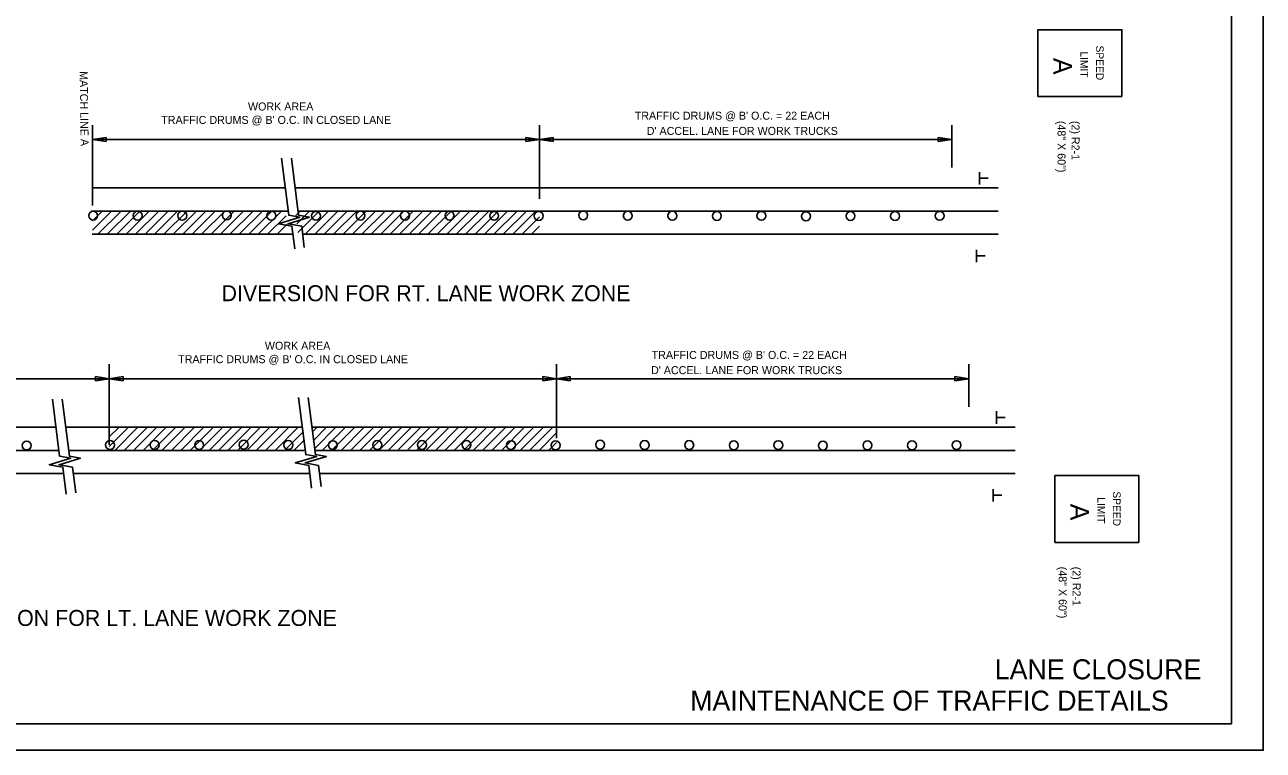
# Model space of a CAD drawing. Extents: x 1374897 to 1375063, y 381144 to 381251.
# Drawn here: x 1374970.4 to 1375063.2, y 381144.3 to 381198.7 of the extents above; entities that cross this region are included whole.
import ezdxf

# ---------------------------------------------------------------- set-up
doc = ezdxf.new("R2010")
doc.units = 0
for name, color, linetype in [('Default', 7, 'Continuous'), ('R_Border', 7, 'Continuous'), ('R_No Plot', 7, 'Continuous')]:
    doc.layers.add(name, color=color, linetype=linetype)

msp = doc.modelspace()

# ---------------------------------------------------------------- linework, layer by layer
at = {"layer": 'Default'}
for p, q in [((1374975.438, 381191.172), (1374975.438, 381185.137)), ((1375008.973, 381191.172), (1375008.973, 381185.637)), ((1375039.883, 381191.172), (1375039.883, 381187.98)), ((1374975.438, 381190.093), (1374976.468, 381190.248)), ((1374975.438, 381190.24), (1374975.438, 381185.137)), ((1374975.438, 381190.24), (1374975.438, 381185.137)), ((1374975.438, 381190.24), (1374975.438, 381185.137)), ((1374976.468, 381190.248), (1374976.468, 381189.938)), ((1375007.943, 381189.938), (1375007.943, 381190.247)), ((1375007.943, 381190.247), (1375008.973, 381190.093)), ((1375008.973, 381190.093), (1375010.003, 381190.248)), ((1375010.003, 381190.248), (1375010.003, 381189.938)), ((1375038.853, 381189.938), (1375038.853, 381190.248)), ((1375038.853, 381190.248), (1375039.883, 381190.093)), ((1375008.973, 381190.093), (1374975.438, 381190.093)), ((1374976.468, 381189.938), (1374975.438, 381190.093)), ((1375008.973, 381190.093), (1375007.943, 381189.938)), ((1375039.883, 381190.093), (1375008.973, 381190.093)), ((1375010.003, 381189.938), (1375008.973, 381190.093)), ((1375039.883, 381190.093), (1375038.853, 381189.938)), ((1375041.97, 381186.716), (1375041.97, 381187.643)), ((1375041.984, 381187.178), (1375042.617, 381187.178)), ((1374975.438, 381186.456), (1374989.916, 381186.456)), ((1374990.634, 381186.456), (1375008.973, 381186.456)), ((1375008.973, 381186.456), (1375043.362, 381186.456)), ((1374975.368, 381184.717), (1374990.061, 381184.717)), ((1374975.439, 381183.278), (1374976.878, 381184.717)), ((1374975.439, 381183.985), (1374976.171, 381184.717)), ((1374975.847, 381182.979), (1374977.585, 381184.717)), ((1374976.554, 381182.979), (1374978.347, 381184.773)), ((1374977.261, 381182.979), (1374978.999, 381184.717)), ((1374977.968, 381182.979), (1374979.706, 381184.717)), ((1374978.675, 381182.979), (1374980.413, 381184.717)), ((1374979.382, 381182.979), (1374981.12, 381184.717)), ((1374980.089, 381182.979), (1374981.827, 381184.717)), ((1374980.796, 381182.979), (1374982.535, 381184.717)), ((1374981.503, 381182.979), (1374983.242, 381184.717)), ((1374982.211, 381182.979), (1374983.949, 381184.717)), ((1374982.918, 381182.979), (1374984.656, 381184.717)), ((1374983.625, 381182.979), (1374985.363, 381184.717)), ((1374984.332, 381182.979), (1374986.07, 381184.717)), ((1374985.039, 381182.979), (1374986.777, 381184.717)), ((1374985.746, 381182.979), (1374987.484, 381184.717)), ((1374986.453, 381182.979), (1374988.191, 381184.717)), ((1374987.16, 381182.979), (1374988.899, 381184.717)), ((1374987.867, 381182.979), (1374989.606, 381184.717)), ((1374990.689, 381184.387), (1374991.02, 381184.717)), ((1374990.765, 381183.755), (1374991.727, 381184.717)), ((1374990.841, 381183.124), (1374992.434, 381184.717)), ((1374990.851, 381184.717), (1375008.973, 381184.717)), ((1374991.403, 381182.979), (1374993.141, 381184.717)), ((1374992.11, 381182.979), (1374993.848, 381184.717)), ((1374992.817, 381182.979), (1374994.555, 381184.717)), ((1374993.524, 381182.979), (1374995.263, 381184.717)), ((1374994.231, 381182.979), (1374995.97, 381184.717)), ((1374994.938, 381182.979), (1374996.677, 381184.717)), ((1374995.646, 381182.979), (1374997.384, 381184.717)), ((1374996.353, 381182.979), (1374998.091, 381184.717)), ((1374997.06, 381182.979), (1374998.798, 381184.717)), ((1374997.767, 381182.979), (1374999.505, 381184.717)), ((1374998.474, 381182.979), (1375000.212, 381184.717)), ((1374999.181, 381182.979), (1375000.919, 381184.717)), ((1374999.888, 381182.979), (1375001.626, 381184.717)), ((1375000.595, 381182.979), (1375002.334, 381184.717)), ((1375001.302, 381182.979), (1375003.041, 381184.717)), ((1375002.01, 381182.979), (1375003.748, 381184.717)), ((1375002.717, 381182.979), (1375004.455, 381184.717)), ((1375003.424, 381182.979), (1375005.162, 381184.717)), ((1375004.131, 381182.979), (1375005.869, 381184.717)), ((1375004.838, 381182.979), (1375006.576, 381184.717)), ((1375005.545, 381182.979), (1375007.283, 381184.717)), ((1375006.252, 381182.979), (1375007.99, 381184.717)), ((1375006.959, 381182.979), (1375008.698, 381184.717)), ((1375008.973, 381184.717), (1375043.362, 381184.717)), ((1374988.574, 381182.979), (1374989.963, 381184.367)), ((1374989.282, 381182.979), (1374990.039, 381183.736)), ((1375007.666, 381182.979), (1375008.973, 381184.286)), ((1374975.416, 381182.979), (1374990.477, 381182.979)), ((1374991.242, 381182.979), (1375008.973, 381182.979)), ((1375008.373, 381182.979), (1375008.973, 381183.579)), ((1375008.973, 381182.979), (1375043.362, 381182.979)), ((1375041.73, 381180.889), (1375041.73, 381181.817)), ((1375041.744, 381181.351), (1375042.377, 381181.351)), ((1374976.707, 381173.23), (1374976.707, 381167.195)), ((1375010.242, 381173.23), (1375010.242, 381167.695)), ((1375041.153, 381173.23), (1375041.153, 381170.038)), ((1374976.707, 381172.151), (1374945.797, 381172.151)), ((1374975.677, 381171.997), (1374975.677, 381172.306)), ((1374975.677, 381172.306), (1374976.707, 381172.151)), ((1374976.707, 381172.151), (1374975.677, 381171.997)), ((1374976.707, 381172.151), (1374977.737, 381172.306)), ((1374976.707, 381172.299), (1374976.707, 381167.195)), ((1374976.707, 381172.298), (1374976.707, 381167.195)), ((1374976.707, 381172.298), (1374976.707, 381167.195)), ((1375010.242, 381172.151), (1374976.707, 381172.151)), ((1374977.737, 381171.997), (1374976.707, 381172.151)), ((1374977.737, 381172.306), (1374977.737, 381171.997)), ((1375009.212, 381171.997), (1375009.212, 381172.306)), ((1375009.212, 381172.306), (1375010.242, 381172.151)), ((1375010.242, 381172.151), (1375009.212, 381171.997)), ((1375010.242, 381172.151), (1375011.272, 381172.306)), ((1375041.153, 381172.151), (1375010.242, 381172.151)), ((1375011.272, 381171.997), (1375010.242, 381172.151)), ((1375011.272, 381172.306), (1375011.272, 381171.997)), ((1375040.122, 381171.997), (1375040.122, 381172.306)), ((1375040.122, 381172.306), (1375041.153, 381172.151)), ((1375041.153, 381172.151), (1375040.122, 381171.997)), ((1375043.239, 381168.775), (1375043.239, 381169.702)), ((1375043.253, 381169.236), (1375043.886, 381169.236)), ((1374945.816, 381168.514), (1374972.709, 381168.514)), ((1374973.438, 381168.514), (1374976.707, 381168.514)), ((1374976.707, 381168.514), (1374991.185, 381168.514)), ((1374976.707, 381167.075), (1374978.146, 381168.514)), ((1374976.707, 381167.782), (1374977.439, 381168.514)), ((1374977.115, 381166.776), (1374978.853, 381168.514)), ((1374977.822, 381166.776), (1374979.616, 381168.569)), ((1374978.529, 381166.776), (1374980.268, 381168.514)), ((1374979.237, 381166.776), (1374980.975, 381168.514)), ((1374979.944, 381166.776), (1374981.682, 381168.514)), ((1374980.651, 381166.776), (1374982.389, 381168.514)), ((1374981.358, 381166.776), (1374983.096, 381168.514)), ((1374982.065, 381166.776), (1374983.803, 381168.514)), ((1374982.772, 381166.776), (1374984.51, 381168.514)), ((1374983.479, 381166.776), (1374985.217, 381168.514)), ((1374984.186, 381166.776), (1374985.925, 381168.514)), ((1374984.893, 381166.776), (1374986.632, 381168.514)), ((1374985.6, 381166.776), (1374987.339, 381168.514)), ((1374986.308, 381166.776), (1374988.046, 381168.514)), ((1374987.015, 381166.776), (1374988.753, 381168.514)), ((1374987.722, 381166.776), (1374989.46, 381168.514)), ((1374988.429, 381166.776), (1374990.167, 381168.514)), ((1374989.136, 381166.776), (1374990.874, 381168.514)), ((1374989.843, 381166.776), (1374991.232, 381168.164)), ((1374991.903, 381168.514), (1375010.242, 381168.514)), ((1374991.958, 381168.183), (1374992.288, 381168.514)), ((1374992.034, 381167.552), (1374992.996, 381168.514)), ((1374992.11, 381166.921), (1374993.703, 381168.514)), ((1374992.672, 381166.776), (1374994.41, 381168.514)), ((1374993.379, 381166.776), (1374995.117, 381168.514)), ((1374994.086, 381166.776), (1374995.824, 381168.514)), ((1374994.793, 381166.776), (1374996.531, 381168.514)), ((1374995.5, 381166.776), (1374997.238, 381168.514)), ((1374996.207, 381166.776), (1374997.945, 381168.514)), ((1374996.914, 381166.776), (1374998.652, 381168.514)), ((1374997.621, 381166.776), (1374999.36, 381168.514)), ((1374998.328, 381166.776), (1375000.067, 381168.514)), ((1374999.035, 381166.776), (1375000.774, 381168.514)), ((1374999.743, 381166.776), (1375001.481, 381168.514)), ((1375000.45, 381166.776), (1375002.188, 381168.514)), ((1375001.157, 381166.776), (1375002.895, 381168.514)), ((1375001.864, 381166.776), (1375003.602, 381168.514)), ((1375002.571, 381166.776), (1375004.309, 381168.514)), ((1375003.278, 381166.776), (1375005.016, 381168.514)), ((1375003.985, 381166.776), (1375005.724, 381168.514)), ((1375004.692, 381166.776), (1375006.431, 381168.514)), ((1375005.399, 381166.776), (1375007.138, 381168.514)), ((1375006.107, 381166.776), (1375007.845, 381168.514)), ((1375006.814, 381166.776), (1375008.552, 381168.514)), ((1375007.521, 381166.776), (1375009.259, 381168.514)), ((1375008.228, 381166.776), (1375009.966, 381168.514)), ((1375008.935, 381166.776), (1375010.242, 381168.083)), ((1375010.242, 381168.514), (1375044.631, 381168.514)), ((1374990.55, 381166.776), (1374991.308, 381167.533)), ((1375009.642, 381166.776), (1375010.242, 381167.375)), ((1374945.726, 381166.776), (1374972.927, 381166.776)), ((1374973.655, 381166.776), (1374976.637, 381166.776)), ((1374976.637, 381166.776), (1374991.33, 381166.776)), ((1374992.121, 381166.776), (1375010.242, 381166.776)), ((1375010.242, 381166.776), (1375044.631, 381166.776)), ((1374945.775, 381165.037), (1374973.281, 381165.037)), ((1374974.01, 381165.037), (1374976.685, 381165.037)), ((1374976.685, 381165.037), (1374991.746, 381165.037)), ((1374992.511, 381165.037), (1375010.242, 381165.037)), ((1375010.242, 381165.037), (1375044.631, 381165.037)), ((1375042.999, 381162.948), (1375042.999, 381163.875)), ((1375043.013, 381163.409), (1375043.646, 381163.409))]:
    msp.add_line(p, q, dxfattribs=at)
for points in [[(1375052.649, 381193.312), (1375046.346, 381193.312), (1375046.346, 381198.312), (1375052.649, 381198.312)], [(1375053.918, 381159.878), (1375047.616, 381159.878), (1375047.616, 381164.878), (1375053.918, 381164.878)]]:
    msp.add_lwpolyline(points, close=True, dxfattribs=at)
for points in [[(1374989.628, 381188.677), (1374990.162, 381184.402), (1374990.988, 381184.256), (1374989.385, 381183.77), (1374990.405, 381183.576), (1374990.608, 381181.891)], [(1374990.357, 381188.677), (1374990.891, 381184.402), (1374991.716, 381184.256), (1374990.114, 381183.77), (1374991.134, 381183.576), (1374991.324, 381181.995)], [(1374990.897, 381170.736), (1374991.432, 381166.46), (1374992.257, 381166.314), (1374990.655, 381165.828), (1374991.674, 381165.634), (1374991.877, 381163.949)], [(1374991.626, 381170.736), (1374992.16, 381166.46), (1374992.986, 381166.314), (1374991.383, 381165.828), (1374992.403, 381165.634), (1374992.593, 381164.053)], [(1374972.448, 381170.608), (1374972.982, 381166.333), (1374973.808, 381166.187), (1374972.205, 381165.701), (1374973.225, 381165.507), (1374973.466, 381163.499)], [(1374973.176, 381170.608), (1374973.71, 381166.333), (1374974.536, 381166.187), (1374972.933, 381165.701), (1374973.953, 381165.507), (1374974.184, 381163.586)]]:
    msp.add_lwpolyline(points, dxfattribs=at)
for centre in [(1374975.493, 381184.375), (1374978.834, 381184.375), (1374982.175, 381184.376), (1374985.516, 381184.396), (1374988.858, 381184.375), (1374992.199, 381184.364), (1374995.54, 381184.38), (1374998.881, 381184.38), (1375002.222, 381184.38), (1375005.563, 381184.364), (1375008.904, 381184.352), (1375012.245, 381184.4), (1375015.586, 381184.368), (1375018.927, 381184.368), (1375022.268, 381184.352), (1375025.609, 381184.365), (1375028.95, 381184.33), (1375032.291, 381184.352), (1375035.632, 381184.349), (1375038.973, 381184.365), (1374970.508, 381167.136), (1374976.762, 381167.178), (1374980.103, 381167.178), (1374983.445, 381167.178), (1374986.786, 381167.199), (1374990.127, 381167.177), (1374993.468, 381167.167), (1374996.809, 381167.183), (1375000.15, 381167.183), (1375003.491, 381167.183), (1375006.832, 381167.167), (1375010.173, 381167.154), (1375013.514, 381167.203), (1375016.855, 381167.171), (1375020.196, 381167.171), (1375023.537, 381167.154), (1375026.878, 381167.168), (1375030.219, 381167.132), (1375033.56, 381167.155), (1375036.901, 381167.152), (1375040.242, 381167.167)]:
    msp.add_circle(centre, 0.333, dxfattribs=at)
at = {"layer": 'R_Border'}
for q in [(1375060.865, 381249.01), (1374902.775, 381146.28)]:
    msp.add_line((1375060.865, 381146.28), q, dxfattribs=at)
at = {"layer": 'R_No Plot'}
msp.add_line((1374896.575, 381144.291), (1375063.241, 381144.291), dxfattribs=at)
for points in [[(1374896.571, 381250.958), (1375063.241, 381250.958), (1375063.241, 381144.289), (1374896.571, 381144.289)], [(1375019.735, 381249.01), (1375029.545, 381249.01), (1375029.545, 381244.07), (1375037.601, 381244.07), (1375049.201, 381244.07), (1375049.201, 381231.904), (1375060.865, 381231.904), (1375060.865, 381146.28), (1374902.775, 381146.28), (1374902.775, 381249.01)]]:
    msp.add_lwpolyline(points, close=True, dxfattribs=at)

# ---------------------------------------------------------------- texts
at = {"layer": 'Default'}
for s, height, rotation, p in [('SPEED', 0.5729, 270, (1375050.702, 381197.131)), ('A', 1.396, 270, (1375047.509, 381196.204)), ('LIMIT', 0.5729, 270, (1375049.531, 381196.689)), ('MATCH LINE A', 0.6, 270.80593, (1374974.481, 381195.211)), ('(48" X 60")', 0.6, 270, (1375047.816, 381191.484)), ('(2) R2-1', 0.6, 270, (1375048.863, 381191.484)), ('SPEED', 0.5729, 270, (1375051.971, 381163.697)), ('A', 1.396, 270, (1375048.778, 381162.77)), ('LIMIT', 0.5729, 270, (1375050.8, 381163.255)), ('(48" X 60")', 0.6, 270, (1375047.9, 381158.05)), ('(2) R2-1', 0.6, 270, (1375048.947, 381158.05))]:
    msp.add_text(s, height=height, rotation=rotation, dxfattribs=at).set_placement(p)
for s, height, p in [('WORK AREA', 0.6, (1374987.105, 381192.262)), ("TRAFFIC DRUMS @ B' O.C. = 22 EACH", 0.6, (1375016.11, 381191.573)), ("TRAFFIC DRUMS @ B' O.C. IN CLOSED LANE", 0.6, (1374980.601, 381191.254)), ("D' ACCEL. LANE FOR WORK TRUCKS", 0.6, (1375017.01, 381190.43)), ('DIVERSION FOR RT. LANE WORK ZONE', 1.2, (1374985.119, 381177.958)), ('WORK AREA', 0.6, (1374988.374, 381174.32)), ("TRAFFIC DRUMS @ B' O.C. IN CLOSED LANE", 0.6, (1374981.87, 381173.312)), ("TRAFFIC DRUMS @ B' O.C. = 22 EACH", 0.6, (1375017.379, 381173.631)), ("D' ACCEL. LANE FOR WORK TRUCKS", 0.6, (1375017.332, 381172.489)), ('DIVERSION FOR LT. LANE WORK ZONE', 1.2, (1374963.37, 381153.608))]:
    msp.add_text(s, height=height, dxfattribs=at).set_placement(p)
at = {"layer": 'R_Border'}
for s, p in [('LANE CLOSURE', (1375043.109, 381149.608)), ('MAINTENANCE OF TRAFFIC DETAILS', (1375020.266, 381147.26))]:
    msp.add_text(s, height=1.5, dxfattribs=at).set_placement(p)

doc.saveas('drawing.dxf')
